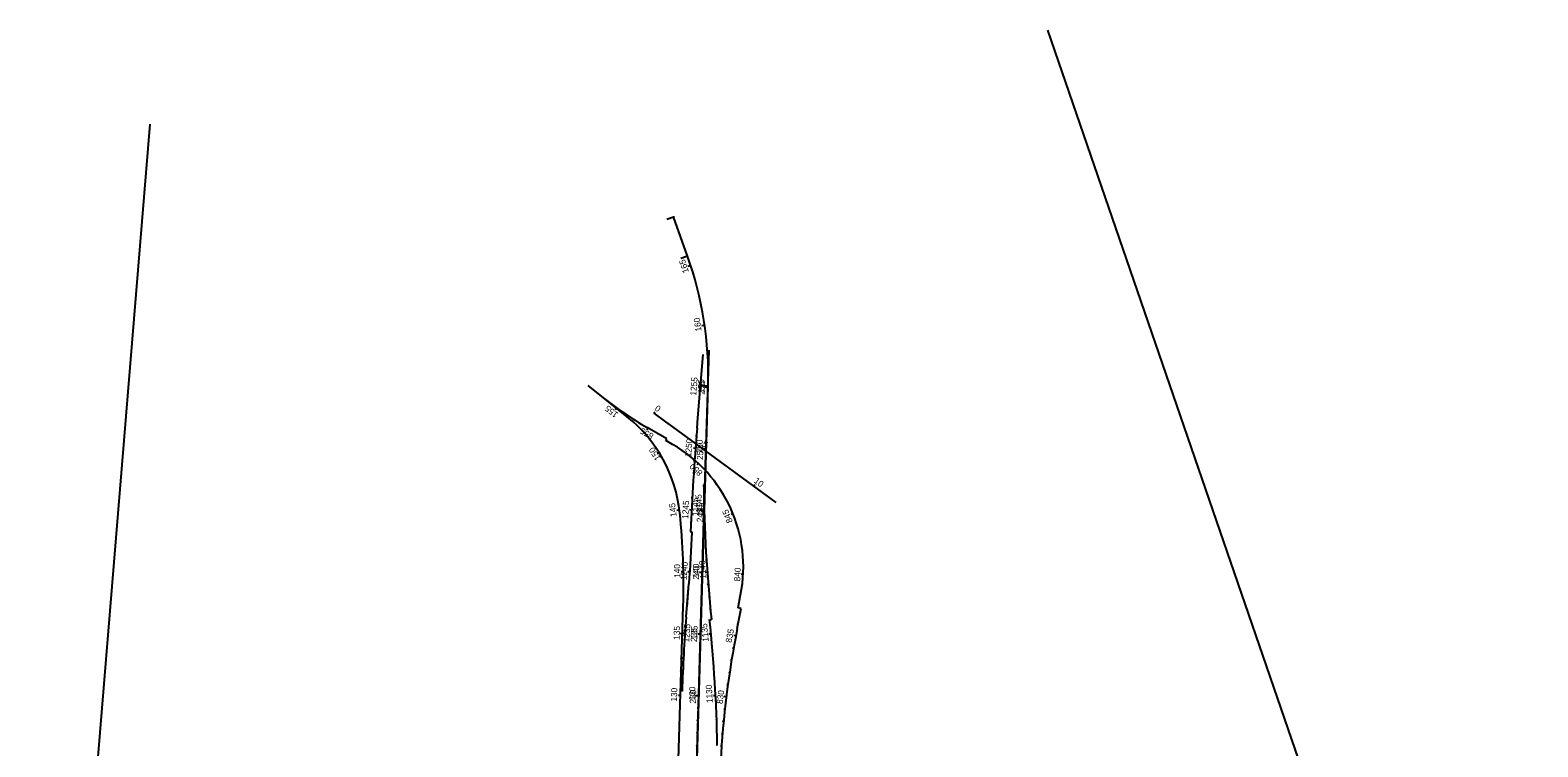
# Model space of a CAD drawing. Extents: x 448091 to 665917, y 1461380 to 1587607.
# Drawn here: x 551430 to 563642, y 1469675 to 1475473 of the extents above; entities that cross this region are included whole.
import ezdxf

# ---------------------------------------------------------------- set-up
doc = ezdxf.new("R2010")
doc.units = 0
for name, color, linetype in [('Barricade3', 7, 'Continuous'), ('Barricade4', 7, 'Continuous'), ('BarrierWall_ep', 7, 'Continuous'), ('BarrierWall_ex', 7, 'Continuous'), ('TextShtNo', 7, 'Continuous'), ('TextTitle', 7, 'Continuous')]:
    doc.layers.add(name, color=color, linetype=linetype)

msp = doc.modelspace()

# ---------------------------------------------------------------- linework, layer by layer
at = {"layer": 'Barricade3'}
for p, q in [((556647, 1473947), (556642, 1473945)), ((556681, 1473853), (556676, 1473851)), ((556714, 1473759), (556710, 1473757)), ((556748, 1473664), (556743, 1473663)), ((556781, 1473570), (556757, 1473562)), ((556810, 1473474), (556805, 1473473)), ((556836, 1473378), (556831, 1473377)), ((556859, 1473280), (556854, 1473279)), ((556894, 1473084), (556870, 1473080)), ((556878, 1473182), (556873, 1473181)), ((556907, 1472984), (556902, 1472984)), ((556916, 1472885), (556911, 1472884)), ((556875, 1472787), (556868, 1472787)), ((556921, 1472785), (556916, 1472785)), ((556867, 1472687), (556860, 1472688)), ((556923, 1472685), (556918, 1472685)), ((556022, 1472540), (556018, 1472534)), ((556101, 1472477), (556096, 1472472)), ((556101, 1472477), (556097, 1472471)), ((556859, 1472587), (556842, 1472589)), ((556851, 1472488), (556844, 1472488)), ((556922, 1472585), (556897, 1472586)), ((556919, 1472485), (556914, 1472485)), ((556179, 1472415), (556168, 1472401)), ((556181, 1472417), (556177, 1472411)), ((556257, 1472352), (556252, 1472347)), ((556263, 1472360), (556259, 1472354)), ((556483, 1472373), (556492, 1472386)), ((556843, 1472388), (556836, 1472389)), ((556916, 1472385), (556911, 1472385)), ((556333, 1472287), (556328, 1472282)), ((556347, 1472306), (556344, 1472300)), ((556433, 1472255), (556425, 1472240)), ((556564, 1472314), (556566, 1472317)), ((556644, 1472255), (556646, 1472258)), ((556834, 1472288), (556827, 1472289)), ((556913, 1472285), (556908, 1472285)), ((556403, 1472216), (556398, 1472211)), ((556467, 1472139), (556461, 1472135)), ((556520, 1472205), (556516, 1472199)), ((556599, 1472142), (556596, 1472136)), ((556725, 1472196), (556730, 1472203)), ((556806, 1472137), (556811, 1472144)), ((556826, 1472189), (556819, 1472189)), ((556910, 1472185), (556905, 1472185)), ((556523, 1472057), (556509, 1472048)), ((556685, 1472091), (556681, 1472085)), ((556766, 1472033), (556762, 1472027)), ((556819, 1472089), (556802, 1472090)), ((556811, 1471989), (556804, 1471990)), ((556907, 1472085), (556882, 1472086)), ((556886, 1472078), (556896, 1472091)), ((556904, 1471985), (556899, 1471985)), ((556967, 1472019), (556969, 1472022)), ((556573, 1471970), (556566, 1471966)), ((556614, 1471879), (556607, 1471876)), ((556805, 1471889), (556798, 1471890)), ((556842, 1471968), (556831, 1471955)), ((556901, 1471885), (556896, 1471885)), ((556912, 1471896), (556907, 1471892)), ((557048, 1471960), (557050, 1471963)), ((557129, 1471901), (557131, 1471904)), ((556647, 1471784), (556641, 1471782)), ((556798, 1471790), (556791, 1471790)), ((556886, 1471786), (556878, 1471786)), ((556898, 1471785), (556893, 1471786)), ((556976, 1471819), (556970, 1471815)), ((557209, 1471842), (557212, 1471845)), ((557290, 1471783), (557300, 1471796)), ((556672, 1471688), (556666, 1471686)), ((556792, 1471690), (556785, 1471690)), ((556887, 1471686), (556880, 1471686)), ((556895, 1471685), (556890, 1471686)), ((557033, 1471737), (557027, 1471733)), ((557082, 1471650), (557076, 1471647)), ((557371, 1471724), (557373, 1471727)), ((557452, 1471665), (557454, 1471668)), ((556689, 1471589), (556667, 1471586)), ((556787, 1471590), (556770, 1471591)), ((556892, 1471585), (556867, 1471586)), ((556889, 1471586), (556872, 1471585)), ((557123, 1471559), (557108, 1471553)), ((556699, 1471490), (556692, 1471489)), ((556707, 1471390), (556700, 1471389)), ((556782, 1471490), (556775, 1471490)), ((556792, 1471390), (556785, 1471390)), ((556886, 1471386), (556881, 1471386)), ((556889, 1471486), (556884, 1471486)), ((556893, 1471486), (556886, 1471486)), ((556887, 1471486), (556889, 1471486)), ((556897, 1471386), (556890, 1471386)), ((557157, 1471465), (557150, 1471463)), ((556713, 1471290), (556706, 1471290)), ((556787, 1471290), (556780, 1471290)), ((556883, 1471286), (556878, 1471286)), ((556902, 1471286), (556895, 1471286)), ((557182, 1471368), (557175, 1471367)), ((557198, 1471269), (557191, 1471269)), ((556718, 1471190), (556711, 1471190)), ((556781, 1471190), (556774, 1471190)), ((556880, 1471186), (556875, 1471186)), ((556908, 1471186), (556901, 1471186)), ((557206, 1471170), (557199, 1471170)), ((556721, 1471090), (556704, 1471090)), ((556774, 1471090), (556757, 1471091)), ((556877, 1471086), (556852, 1471086)), ((556915, 1471087), (556898, 1471085)), ((557206, 1471070), (557188, 1471071)), ((556721, 1470890), (556714, 1470890)), ((556722, 1470990), (556715, 1470990)), ((556751, 1470806), (556766, 1470993)), ((556758, 1470891), (556751, 1470891)), ((556766, 1470990), (556759, 1470991)), ((556871, 1470886), (556866, 1470886)), ((556874, 1470986), (556869, 1470986)), ((556922, 1470987), (556915, 1470986)), ((556931, 1470887), (556924, 1470887)), ((557196, 1470970), (557189, 1470971)), ((556719, 1470790), (556711, 1470791)), ((556750, 1470791), (556743, 1470792)), ((556868, 1470786), (556863, 1470786)), ((556940, 1470788), (556933, 1470787)), ((557157, 1470632), (557190, 1470795)), ((557178, 1470872), (557171, 1470873)), ((557184, 1470769), (557177, 1470770)), ((556716, 1470690), (556708, 1470691)), ((556716, 1470690), (556709, 1470691)), ((556742, 1470691), (556735, 1470692)), ((556866, 1470686), (556861, 1470686)), ((556935, 1470687), (556928, 1470686)), ((557165, 1470671), (557158, 1470672)), ((556713, 1470590), (556691, 1470591)), ((556713, 1470590), (556707, 1470591)), ((556744, 1470591), (556717, 1470593)), ((556863, 1470586), (556838, 1470587)), ((556945, 1470587), (556928, 1470585)), ((557146, 1470573), (557129, 1470576)), ((556710, 1470490), (556702, 1470491)), ((556710, 1470490), (556703, 1470491)), ((556728, 1470492), (556721, 1470492)), ((556860, 1470486), (556855, 1470486)), ((556954, 1470488), (556947, 1470487)), ((557127, 1470474), (557120, 1470475)), ((556704, 1470290), (556696, 1470291)), ((556704, 1470291), (556697, 1470291)), ((556707, 1470390), (556699, 1470391)), ((556707, 1470391), (556700, 1470391)), ((556717, 1470292), (556710, 1470292)), ((556722, 1470392), (556715, 1470392)), ((556854, 1470286), (556849, 1470286)), ((556857, 1470386), (556852, 1470386)), ((556963, 1470388), (556956, 1470387)), ((556970, 1470288), (556963, 1470288)), ((557095, 1470277), (557088, 1470278)), ((557111, 1470376), (557104, 1470377)), ((556701, 1470191), (556693, 1470191)), ((556701, 1470191), (556694, 1470191)), ((556713, 1470192), (556706, 1470193)), ((556851, 1470186), (556846, 1470186)), ((556976, 1470188), (556969, 1470188)), ((557081, 1470178), (557074, 1470179)), ((556698, 1470091), (556681, 1470091)), ((556711, 1470126), (556708, 1470126)), ((556848, 1470086), (556823, 1470087)), ((556982, 1470088), (556965, 1470088)), ((557068, 1470079), (557051, 1470081)), ((556695, 1469991), (556687, 1469991)), ((556695, 1469991), (556688, 1469991)), ((556845, 1469986), (556840, 1469986)), ((556987, 1469989), (556980, 1469988)), ((557056, 1469979), (557049, 1469980)), ((556689, 1469791), (556681, 1469791)), ((556689, 1469791), (556682, 1469791)), ((556692, 1469891), (556684, 1469891)), ((556692, 1469891), (556685, 1469891)), ((556839, 1469786), (556834, 1469786)), ((556842, 1469886), (556837, 1469886)), ((556991, 1469889), (556984, 1469888)), ((556994, 1469789), (556987, 1469788)), ((557046, 1469880), (557039, 1469881)), ((556686, 1469691), (556678, 1469691)), ((556686, 1469691), (556679, 1469691)), ((556836, 1469686), (556831, 1469686)), ((556996, 1469687), (556989, 1469687)), ((557029, 1469681), (557022, 1469681)), ((557037, 1469780), (557030, 1469781))]:
    msp.add_line(p, q, dxfattribs=at)
at = {"layer": 'Barricade4'}
for p, q in [((556755, 1473644), (556642, 1473962)), ((556839, 1472337), (556880, 1472849)), ((556267, 1472345), (555950, 1472597)), ((556795, 1468287), (556922, 1472593)), ((556483, 1472373), (556577, 1472304)), ((556587, 1472166), (556427, 1472258)), ((556577, 1472304), (556633, 1472263)), ((556633, 1472263), (557470, 1471651)), ((556832, 1472252), (556839, 1472337)), ((556579, 1472153), (556587, 1472166)), ((556633, 1472122), (556579, 1472153)), ((556793, 1471412), (556778, 1471413)), ((556744, 1470725), (556766, 1470993)), ((557164, 1470800), (557185, 1470906)), ((556550, 1465093), (556719, 1470813)), ((557157, 1470632), (557190, 1470795)), ((557190, 1470795), (557164, 1470800)), ((556934, 1470704), (556949, 1470705))]:
    msp.add_line(p, q, dxfattribs=at)
for centre, radius, start, end in [((554058, 1472678), 2865, 358.3071, 19.71), ((557857, 1474741), 2865, 231.4039, 240.0527), ((555552, 1471449), 1146, 5.8789, 51.4039), ((579673, 1470377), 22918, 175.3067, 177.4092), ((556061, 1471129), 1146, 348.7511, 60.0527), ((568344, 1471912), 11459, 180.5776, 186.0462), ((550992, 1470980), 5730, 358.3327, 5.8789), ((545346, 1471930), 11459, 355.3067, 357.4092), ((568165, 1469787), 11459, 175.3067, 178.3067), ((545538, 1469497), 11459, 0.9539, 6.0512), ((564650, 1469142), 7639, 168.7511, 176.9291)]:
    msp.add_arc(centre, radius, start, end, dxfattribs=at)
at = {"layer": 'BarrierWall_ep'}
for p, q in [((563642, 1463956), (559672, 1475473)), ((551430, 1462885), (552402, 1474712))]:
    msp.add_line(p, q, dxfattribs=at)
at = {"layer": 'BarrierWall_ex'}
for p, q in [((556641, 1473961), (556587, 1473942)), ((556754, 1473644), (556701, 1473625)), ((556755, 1473646), (556752, 1473645)), ((556921, 1472593), (556864, 1472595))]:
    msp.add_line(p, q, dxfattribs=at)
for centre in [(556642, 1473962), (556755, 1473644), (556922, 1472593)]:
    msp.add_circle(centre, 1, dxfattribs=at)
at = {"layer": 'TextShtNo'}
for p, q in [((556839, 1472337), (556880, 1472849)), ((556911, 1472292), (556929, 1472885)), ((556267, 1472345), (555950, 1472597)), ((556483, 1472373), (556577, 1472304)), ((556587, 1472166), (556427, 1472258)), ((556577, 1472304), (556633, 1472263)), ((556633, 1472263), (557470, 1471651)), ((556832, 1472252), (556839, 1472337)), ((556888, 1471509), (556911, 1472292)), ((556579, 1472153), (556587, 1472166)), ((556633, 1472122), (556579, 1472153)), ((556830, 1469540), (556888, 1471509)), ((556793, 1471412), (556778, 1471413)), ((556744, 1470725), (556766, 1470993)), ((557164, 1470800), (557185, 1470906)), ((556550, 1465093), (556719, 1470813)), ((557157, 1470632), (557190, 1470795)), ((557190, 1470795), (557164, 1470800)), ((556934, 1470704), (556949, 1470705))]:
    msp.add_line(p, q, dxfattribs=at)
for centre, radius, start, end in [((557857, 1474741), 2865, 231.4039, 240.0527), ((555552, 1471449), 1146, 5.8789, 51.4039), ((579673, 1470377), 22918, 175.3067, 177.4092), ((556061, 1471129), 1146, 348.7511, 60.0527), ((568344, 1471912), 11459, 180.5776, 186.0462), ((550992, 1470980), 5730, 358.3327, 5.8789), ((545346, 1471930), 11459, 355.3067, 357.4092), ((568165, 1469787), 11459, 175.3067, 178.3067), ((545538, 1469497), 11459, 0.9539, 6.0512), ((564650, 1469142), 7639, 168.7511, 176.9291)]:
    msp.add_arc(centre, radius, start, end, dxfattribs=at)
at = {"layer": 'TextTitle'}
for p, q in [((556875, 1472787), (556868, 1472787)), ((556926, 1472785), (556917, 1472785)), ((556867, 1472687), (556860, 1472688)), ((556923, 1472685), (556914, 1472685)), ((556022, 1472540), (556018, 1472534)), ((556101, 1472477), (556096, 1472472)), ((556101, 1472477), (556097, 1472471)), ((556859, 1472587), (556842, 1472589)), ((556851, 1472488), (556844, 1472488)), ((556920, 1472585), (556904, 1472586)), ((556917, 1472485), (556908, 1472485)), ((556179, 1472415), (556168, 1472401)), ((556181, 1472417), (556177, 1472411)), ((556257, 1472352), (556252, 1472347)), ((556263, 1472360), (556259, 1472354)), ((556483, 1472373), (556492, 1472386)), ((556843, 1472388), (556836, 1472389)), ((556914, 1472385), (556905, 1472386)), ((556333, 1472287), (556328, 1472282)), ((556347, 1472306), (556344, 1472300)), ((556433, 1472255), (556425, 1472240)), ((556564, 1472314), (556566, 1472317)), ((556644, 1472255), (556646, 1472258)), ((556834, 1472288), (556827, 1472289)), ((556911, 1472285), (556902, 1472286)), ((556403, 1472216), (556398, 1472211)), ((556467, 1472139), (556461, 1472135)), ((556520, 1472205), (556516, 1472199)), ((556599, 1472142), (556596, 1472136)), ((556725, 1472196), (556730, 1472203)), ((556806, 1472137), (556811, 1472144)), ((556826, 1472189), (556819, 1472189)), ((556908, 1472185), (556899, 1472186)), ((556523, 1472057), (556509, 1472048)), ((556685, 1472091), (556681, 1472085)), ((556766, 1472033), (556762, 1472027)), ((556819, 1472089), (556802, 1472090)), ((556811, 1471989), (556804, 1471990)), ((556886, 1472078), (556896, 1472091)), ((556905, 1472085), (556889, 1472086)), ((556902, 1471985), (556893, 1471986)), ((556967, 1472019), (556969, 1472022)), ((556573, 1471970), (556566, 1471966)), ((556614, 1471879), (556607, 1471876)), ((556805, 1471889), (556798, 1471890)), ((556842, 1471968), (556831, 1471955)), ((556899, 1471885), (556890, 1471886)), ((556912, 1471896), (556907, 1471892)), ((557048, 1471960), (557050, 1471963)), ((557129, 1471901), (557131, 1471904)), ((556647, 1471784), (556641, 1471782)), ((556798, 1471790), (556791, 1471790)), ((556886, 1471786), (556878, 1471786)), ((556896, 1471786), (556893, 1471786)), ((556976, 1471819), (556970, 1471815)), ((557209, 1471842), (557212, 1471845)), ((557290, 1471783), (557300, 1471796)), ((556672, 1471688), (556666, 1471686)), ((556792, 1471690), (556785, 1471690)), ((556887, 1471686), (556880, 1471686)), ((556893, 1471686), (556890, 1471686)), ((557033, 1471737), (557027, 1471733)), ((557082, 1471650), (557076, 1471647)), ((557371, 1471724), (557373, 1471727)), ((557452, 1471665), (557454, 1471668)), ((556689, 1471589), (556667, 1471586)), ((556787, 1471590), (556770, 1471591)), ((556889, 1471586), (556872, 1471585)), ((556890, 1471586), (556884, 1471586)), ((557123, 1471559), (557108, 1471553)), ((556699, 1471490), (556692, 1471489)), ((556707, 1471390), (556700, 1471389)), ((556782, 1471490), (556775, 1471490)), ((556792, 1471390), (556785, 1471390)), ((556884, 1471386), (556875, 1471386)), ((556893, 1471486), (556886, 1471486)), ((556887, 1471486), (556889, 1471486)), ((556897, 1471386), (556890, 1471386)), ((557157, 1471465), (557150, 1471463)), ((556713, 1471290), (556706, 1471290)), ((556787, 1471290), (556780, 1471290)), ((556881, 1471286), (556873, 1471286)), ((556902, 1471286), (556895, 1471286)), ((557182, 1471368), (557175, 1471367)), ((557198, 1471269), (557191, 1471269)), ((556718, 1471190), (556711, 1471190)), ((556781, 1471190), (556774, 1471190)), ((556878, 1471186), (556875, 1471186)), ((556908, 1471186), (556901, 1471186)), ((557206, 1471170), (557199, 1471170)), ((556721, 1471090), (556704, 1471090)), ((556774, 1471090), (556757, 1471091)), ((556875, 1471086), (556859, 1471086)), ((556915, 1471087), (556898, 1471085)), ((557206, 1471070), (557188, 1471071)), ((556721, 1470890), (556714, 1470890)), ((556722, 1470990), (556715, 1470990)), ((556751, 1470806), (556766, 1470993)), ((556758, 1470891), (556751, 1470891)), ((556766, 1470990), (556759, 1470991)), ((556869, 1470886), (556861, 1470886)), ((556872, 1470986), (556864, 1470986)), ((556922, 1470987), (556915, 1470986)), ((556931, 1470887), (556924, 1470887)), ((557196, 1470970), (557189, 1470971)), ((556719, 1470790), (556711, 1470791)), ((556750, 1470791), (556743, 1470792)), ((556867, 1470786), (556858, 1470786)), ((556940, 1470788), (556933, 1470787)), ((557157, 1470632), (557190, 1470795)), ((557178, 1470872), (557171, 1470873)), ((557184, 1470769), (557177, 1470770)), ((556716, 1470690), (556708, 1470691)), ((556716, 1470690), (556709, 1470691)), ((556742, 1470691), (556735, 1470692)), ((556864, 1470686), (556855, 1470686)), ((556935, 1470687), (556928, 1470686)), ((557165, 1470671), (557158, 1470672)), ((556713, 1470590), (556691, 1470591)), ((556713, 1470590), (556707, 1470591)), ((556744, 1470591), (556717, 1470593)), ((556861, 1470586), (556840, 1470587)), ((556945, 1470587), (556928, 1470585)), ((557146, 1470573), (557129, 1470576)), ((556710, 1470490), (556702, 1470491)), ((556710, 1470490), (556703, 1470491)), ((556728, 1470492), (556721, 1470492)), ((556858, 1470486), (556849, 1470486)), ((556954, 1470488), (556947, 1470487)), ((557127, 1470474), (557120, 1470475)), ((556704, 1470290), (556696, 1470291)), ((556704, 1470291), (556697, 1470291)), ((556707, 1470390), (556699, 1470391)), ((556707, 1470391), (556700, 1470391)), ((556717, 1470292), (556710, 1470292)), ((556722, 1470392), (556715, 1470392)), ((556852, 1470286), (556843, 1470286)), ((556855, 1470386), (556846, 1470386)), ((556963, 1470388), (556956, 1470387)), ((556970, 1470288), (556963, 1470288)), ((557095, 1470277), (557088, 1470278)), ((557111, 1470376), (557104, 1470377)), ((556701, 1470191), (556693, 1470191)), ((556701, 1470191), (556694, 1470191)), ((556713, 1470192), (556706, 1470193)), ((556849, 1470186), (556840, 1470186)), ((556976, 1470188), (556969, 1470188)), ((557081, 1470178), (557074, 1470179)), ((556698, 1470091), (556681, 1470091)), ((556711, 1470126), (556708, 1470126)), ((556846, 1470086), (556830, 1470087)), ((556982, 1470088), (556965, 1470088)), ((557068, 1470079), (557051, 1470081)), ((556695, 1469991), (556687, 1469991)), ((556695, 1469991), (556688, 1469991)), ((556843, 1469986), (556834, 1469987)), ((556987, 1469989), (556980, 1469988)), ((557056, 1469979), (557049, 1469980)), ((556689, 1469791), (556681, 1469791)), ((556689, 1469791), (556682, 1469791)), ((556692, 1469891), (556684, 1469891)), ((556692, 1469891), (556685, 1469891)), ((556837, 1469786), (556828, 1469787)), ((556840, 1469886), (556831, 1469887)), ((556991, 1469889), (556984, 1469888)), ((556994, 1469789), (556987, 1469788)), ((557046, 1469880), (557039, 1469881)), ((556686, 1469691), (556678, 1469691)), ((556686, 1469691), (556679, 1469691)), ((556834, 1469686), (556825, 1469687)), ((556996, 1469687), (556989, 1469687)), ((557029, 1469681), (557022, 1469681)), ((557037, 1469780), (557030, 1469781))]:
    msp.add_line(p, q, dxfattribs=at)

# ---------------------------------------------------------------- texts
at = {"layer": 'Barricade3'}
for s, rotation, p in [('165', 108.1416, (556767, 1473517)), ('160', 98.1416, (556869, 1473039)), ('1255', 85.3067, (556825, 1472515)), ('155', 88.3071, (556889, 1472536)), ('155', 141.4039, (556198, 1472372)), ('0', 323.8453, (556484, 1472402)), ('855', 150.0527, (556485, 1472203)), ('1250', 85.7166, (556784, 1472017)), ('150', 88.3071, (556875, 1472048)), ('5', 323.8453, (556866, 1472115)), ('150', 122.0175, (556540, 1472010)), ('850', 137.0229, (556881, 1471897)), ('10', 323.8452, (557288, 1471816)), ('145', 97.0176, (556667, 1471539)), ('1245', 86.9666, (556760, 1471518)), ('1145', 91.632, (556845, 1471542)), ('145', 88.3071, (556880, 1471539)), ('845', 112.0229, (557122, 1471497)), ('140', 91.1067, (556697, 1471042)), ('1240', 85.7943, (556747, 1471022)), ('140', 88.3071, (556846, 1471044)), ('1140', 94.132, (556908, 1471036)), ('840', 87.0229, (557181, 1471012)), ('135', 88.3067, (556691, 1470540)), ('1235', 85.9745, (556768, 1470519)), ('135', 88.3071, (556833, 1470543)), ('1135', 95.4604, (556927, 1470527)), ('835', 79.2052, (557111, 1470514)), ('130', 88.3067, (556669, 1470040)), ('130', 88.3071, (556815, 1470050)), ('1130', 92.9604, (556959, 1470030)), ('830', 82.9552, (557039, 1470019))]:
    msp.add_text(s, height=50, rotation=rotation, dxfattribs=at).set_placement(p)
at = {"layer": 'BarrierWall_ex'}
for s, rotation, p in [('POT STA. 169+15.61', 199.71, (556636, 1473958)), ('PT STA. 165+78.42', 199.71, (556749, 1473640)), ('PC STA. 155+08.28', 178.3071, (556915, 1472592))]:
    msp.add_text(s, height=3.5, rotation=rotation, dxfattribs=at).set_placement(p)
at = {"layer": 'TextTitle'}
for s, rotation, p in [('1255', 85.3067, (556825, 1472515)), ('255', 88.3067, (556894, 1472522)), ('155', 141.4039, (556198, 1472372)), ('0', 323.8453, (556484, 1472402)), ('855', 150.0527, (556485, 1472203)), ('1250', 85.7166, (556784, 1472017)), ('250', 88.3067, (556880, 1471995)), ('5', 323.8453, (556866, 1472115)), ('150', 122.0175, (556540, 1472010)), ('850', 137.0229, (556881, 1471897)), ('10', 323.8452, (557288, 1471816)), ('145', 97.0176, (556667, 1471539)), ('1245', 86.9666, (556760, 1471518)), ('1145', 91.632, (556873, 1471570)), ('245', 88.3066, (556879, 1471491)), ('845', 112.0229, (557122, 1471497)), ('140', 91.1067, (556697, 1471042)), ('1240', 85.7943, (556747, 1471022)), ('240', 88.3066, (556848, 1471026)), ('1140', 94.132, (556908, 1471036)), ('840', 87.0229, (557181, 1471012)), ('135', 88.3067, (556691, 1470540)), ('1235', 85.9745, (556768, 1470519)), ('1135', 95.4604, (556927, 1470527)), ('235', 88.3066, (556830, 1470522)), ('835', 79.2052, (557111, 1470514)), ('130', 88.3067, (556669, 1470040)), ('1130', 92.9604, (556959, 1470030)), ('230', 88.3067, (556822, 1470024)), ('830', 82.9552, (557039, 1470019))]:
    msp.add_text(s, height=50, rotation=rotation, dxfattribs=at).set_placement(p)

doc.saveas('drawing.dxf')
